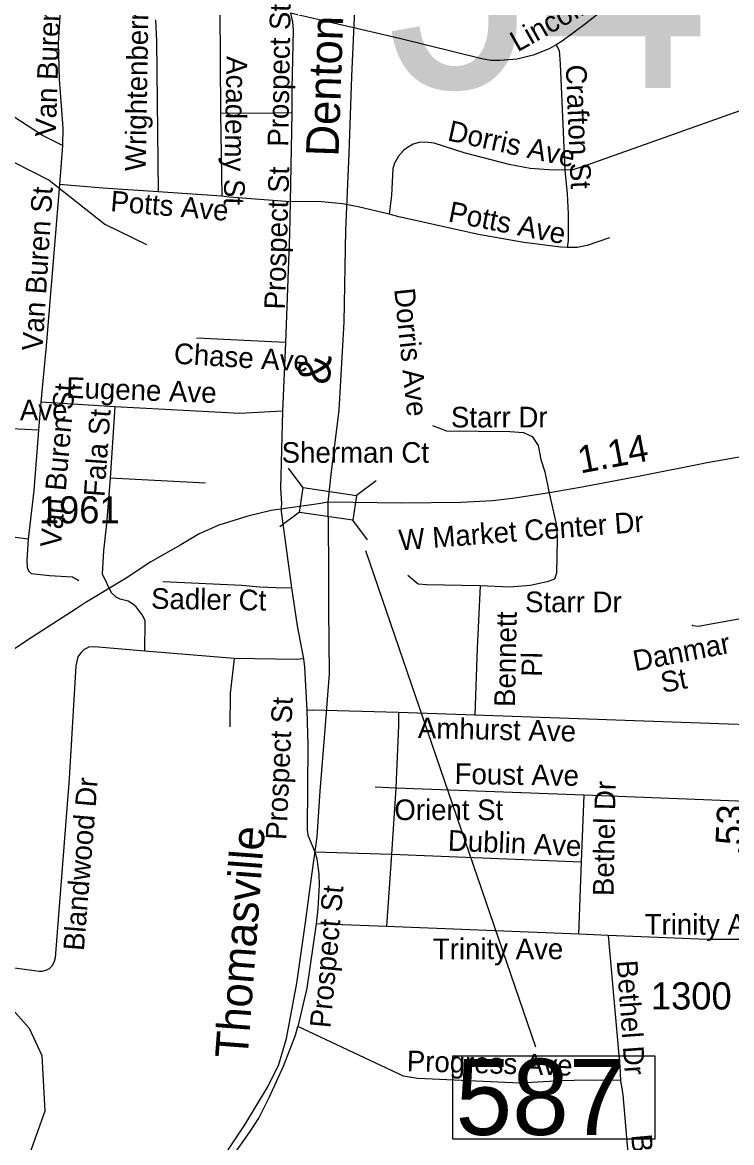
# Model space of a CAD drawing. Extents: x 1662474 to 1856135, y 779280 to 917889.
# Drawn here: x 1695888 to 1699151, y 792320 to 797474 of the extents above; entities that cross this region are included whole.
import ezdxf

# ---------------------------------------------------------------- set-up
doc = ezdxf.new("R2010")
doc.units = 0
for name, color, linetype in [('Exist Hydrographic Misc Water Feature', 7, 'Continuous'), ('Exist Railroad Mainline', 7, 'Continuous'), ('Exist Railroad Mainline Label', 7, 'Continuous'), ('Exist Road Non-System Structure Non-Sys Other Number Label', 7, 'Continuous'), ('Exist Road Non-System Type 51', 7, 'Continuous'), ('Exist Road Non-System Type 51 Label', 7, 'Continuous'), ('Exist Road Secondary Mileage Hundredths English Label', 7, 'Continuous'), ('Exist Road Secondary Mileage Tenths English Label', 7, 'Continuous'), ('Exist Road Secondary Structure Standard Bridge CELL', 7, 'Continuous'), ('Exist Road Secondary Structure Standard Bridge Number Label', 7, 'Continuous'), ('Exist Road Secondary Type 51 Label', 7, 'Continuous'), ('Exist Road Secondary Type 51 Number Label', 7, 'Continuous'), ('Exist Road Secondary Type 51 Undivided 4 Lane Attributed', 7, 'Continuous')]:
    doc.layers.add(name, color=color, linetype=linetype)

msp = doc.modelspace()

# ---------------------------------------------------------------- linework, layer by layer
at = {"layer": 'Exist Hydrographic Misc Water Feature'}
for points in [[(1695762.9, 796874), (1696011.8, 796747.6), (1696267.8, 796545.3), (1696458.8, 796452.8)], [(1690243.7, 793625), (1690261.8, 793742.8), (1690503.7, 793813.4), (1690978.7, 793826.6), (1692288.8, 793921.5), (1692512.8, 793841.5), (1693269.8, 793691.5), (1693377.8, 793623.6), (1693651.8, 793522.9), (1693959.8, 793487.1), (1694548.8, 793222.4), (1695381.8, 793202.2), (1695730.8, 793057.2), (1695919.9, 792846.6), (1695976.9, 792720.7), (1695990.8, 792464.4), (1695921.8, 792272.1)]]:
    msp.add_lwpolyline(points, dxfattribs=at)
at = {"layer": 'Exist Railroad Mainline'}
msp.add_lwpolyline([(1696759.8, 792173), (1696911.1, 792402), (1697014, 792571.6), (1697066.7, 792675.2), (1697103.3, 792799.2), (1697150.8, 793053), (1697190.3, 793332.8), (1697215.4, 793516.8), (1697244.6, 793726.6), (1697257.7, 793936.4), (1697281.6, 794220.5), (1697300.9, 794476.5), (1697298.5, 794772.4), (1697297.5, 794998.7), (1697295.6, 795266), (1697307.9, 795394.4), (1697345.6, 795690.4), (1697367.9, 796094.3), (1697376.2, 796518.6), (1697392.2, 796870.5), (1697404.3, 797224.4), (1697418.1, 797530.7)], dxfattribs=at)
at = {"layer": 'Exist Road Non-System Type 51'}
for p, q in [((1696796.6, 797537), (1696799.2, 797055.7)), ((1696799.2, 797055.7), (1696805.5, 796674.9)), ((1697128.1, 797057.8), (1697119.6, 796648.1)), ((1696072.5, 796907.1), (1696058.9, 796727.9)), ((1696805.5, 796674.9), (1696513.4, 796694.8)), ((1697098.4, 796001.4), (1696689.5, 796020.5)), ((1697098.4, 796001.4), (1697084.5, 795685.6)), ((1695972.8, 795726), (1695962.2, 795597.7)), ((1696313.4, 795704.8), (1695972.8, 795726)), ((1696313.4, 795704.8), (1696292.6, 795376.7)), ((1695962.2, 795597.7), (1695602.1, 795616)), ((1696731, 795354.7), (1696292.6, 795376.7)), ((1697079.2, 795223.2), (1697126.2, 794872.5)), ((1696862.8, 794547.6), (1696451.5, 794580.9)), ((1697618.9, 794300.4), (1697969.9, 794288.8)), ((1697969.9, 794288.8), (1699269, 794241.8)), ((1697606.4, 793951.2), (1697510.8, 793955.2)), ((1697606.4, 793951.2), (1697585.6, 793647.4)), ((1698473.2, 793919.2), (1697606.4, 793951.2)), ((1698460.9, 793612.2), (1698473.2, 793919.2)), ((1699255.9, 793887.8), (1698473.2, 793919.2)), ((1697233.4, 793657.9), (1697585.6, 793647.4)), ((1697585.6, 793647.4), (1697562.5, 793314.2)), ((1697585.6, 793647.4), (1698460.9, 793612.2)), ((1698448.6, 793278.9), (1698460.9, 793612.2)), ((1697562.5, 793314.2), (1697240.4, 793325.9)), ((1698448.6, 793278.9), (1697562.5, 793314.2)), ((1698582.4, 793273.1), (1698448.6, 793278.9))]:
    msp.add_line(p, q, dxfattribs=at)
for points in [[(1698802.4, 798257.2), (1698810, 797982.9), (1698803.1, 797941.2), (1698787.1, 797898.7), (1698732.2, 797797.4), (1698655.4, 797669.9), (1698595, 797580.9), (1698537, 797513.7), (1698479.5, 797468), (1698371.4, 797387.9), (1698343.4, 797371.4)], [(1696099, 797694.2), (1696085.4, 797678.8), (1696077.5, 797653.5), (1696060.4, 797501.6), (1696052.5, 797379.8), (1696056.5, 797213.4), (1696073.5, 796987.4), (1696072.5, 796907.1)], [(1697120.8, 797517.1), (1697130.5, 797476.1), (1697133.6, 797439.9), (1697127.1, 797167.8), (1697128.1, 797057.8)], [(1698343.4, 797371.4), (1698311, 797351.7), (1698237.9, 797323.1), (1698165.1, 797305), (1698084, 797299.2), (1698042.8, 797299.2), (1698001.6, 797306.4), (1697623.6, 797399.8), (1697120.8, 797517.1)], [(1696501.1, 797485), (1696505.6, 797387.9), (1696513.4, 796694.8)], [(1698343.4, 797371.4), (1698356.9, 797344.4), (1698362.5, 797284), (1698383.5, 796794.8)], [(1699559.4, 797199.5), (1698472.6, 796811.9), (1698421, 796795.2), (1698383.5, 796794.8)], [(1696072.5, 796907.1), (1695980.6, 796953.9), (1695689.2, 797141.8)], [(1697128.1, 797057.8), (1696973.8, 797055.1), (1696799.2, 797055.7)], [(1698383.5, 796794.8), (1698310.2, 796795.2), (1698224.9, 796802.4), (1698127.4, 796820.5), (1697920.8, 796873.8), (1697782.1, 796917.6), (1697739.4, 796922.6), (1697714.1, 796921.5), (1697685.6, 796913.2), (1697660.6, 796898.9), (1697642.2, 796884.8), (1697618.4, 796857.8), (1697600.5, 796826.2), (1697592.6, 796801.1), (1697585.9, 796677.7), (1697575.4, 796591.6)], [(1698383.5, 796794.8), (1698394.2, 796685.9), (1698399.2, 796593.8), (1698398.6, 796469.9), (1698394.5, 796438.1)], [(1696058.9, 796727.9), (1695997.4, 795985.4), (1695972.8, 795726)], [(1696513.4, 796694.8), (1696258.9, 796710.8), (1696058.9, 796727.9)], [(1697119.6, 796648.1), (1696839.1, 796669.9), (1696805.5, 796674.9)], [(1697119.6, 796648.1), (1697117.4, 796499.5), (1697098.4, 796001.4)], [(1697575.4, 796591.6), (1697432.6, 796625.2), (1697360.9, 796638.9), (1697263.5, 796648.1), (1697161.6, 796649.9), (1697119.6, 796648.1)], [(1698394.5, 796438.1), (1698365.9, 796439.4), (1698194.8, 796461.4), (1697987.1, 796497.4), (1697620, 796579.5), (1697575.4, 796591.6)], [(1698589, 796482.4), (1698485.9, 796448.1), (1698440.6, 796438.6), (1698394.5, 796438.1)], [(1697084.5, 795685.6), (1696887.9, 795673.8), (1696313.4, 795704.8)], [(1697084.5, 795685.6), (1697075.4, 795328.9), (1697080.9, 795261.2), (1697079, 795242.4), (1697079.2, 795223.2)], [(1695962.2, 795597.7), (1695941, 795319.8), (1695914.8, 795095.9)], [(1697775.1, 795618.9), (1697838.6, 795594.2), (1698130.4, 795591.1), (1698192.9, 795587.7), (1698233.6, 795569.4), (1698261.6, 795526.9), (1698273.8, 795462.5), (1698291.9, 795406.9), (1698311.6, 795308.4)], [(1696292.6, 795376.7), (1696275.1, 795166.7), (1696261.4, 795043.4), (1696254.4, 794936.8), (1696296.9, 794851.2)], [(1698311.6, 795308.4), (1698343.1, 795166.2), (1698349.1, 795098.5), (1698346.1, 794940.5), (1698335.6, 794911.9), (1698302.4, 794899.8), (1698224.1, 794883), (1698130.8, 794875.7), (1697993.6, 794881.4)], [(1695914.8, 795095.9), (1695843.9, 795105), (1695580.4, 795122.6)], [(1695914.8, 795095.9), (1695908.1, 795000.1), (1695909.5, 794967.5), (1695916.1, 794950.2), (1695927.9, 794938.4), (1696012.1, 794928.9), (1696118.4, 794922.6), (1696147, 794906.6)], [(1697993.6, 794881.4), (1697747.2, 794886.7), (1697709.5, 794889), (1697661.4, 794928.7)], [(1697126.2, 794872.5), (1697090.1, 794870.4), (1696980.9, 794875.4), (1696897.1, 794883.8), (1696534.9, 794899.5)], [(1697126.2, 794872.5), (1697152, 794696.9), (1697181.4, 794545.2)], [(1697993.6, 794881.4), (1697980.4, 794594.2), (1697969.9, 794288.8)], [(1696451.5, 794580.9), (1696452.2, 794722.6), (1696438.6, 794748.9), (1696412.1, 794784.6), (1696395.4, 794799.2), (1696374.4, 794811.6), (1696337.9, 794820.5), (1696319.5, 794829.4), (1696296.9, 794851.2)], [(1699302.6, 794750.4), (1698997.4, 794695.1), (1698972.4, 794697.4), (1698968.2, 794702.7)], [(1696451.5, 794580.9), (1696220, 794601.4), (1696193.8, 794599.8), (1696172.8, 794589.2), (1696156.5, 794573), (1696143.4, 794555.4), (1696133.9, 794513.7), (1696103.1, 793995.6), (1696038.4, 793170.2), (1696034.9, 793152.6), (1696025.5, 793133.9), (1696010.6, 793119.5), (1695998.8, 793112.9), (1695978.8, 793107.4), (1695964.9, 793107.9), (1695491.9, 793171.2), (1695468, 793185.4), (1695450.1, 793206.7), (1695442.1, 793227.1), (1695439.9, 793243.9), (1695420, 794000.6), (1695415.5, 794088), (1695411.6, 794103.5)], [(1696862.8, 794547.6), (1696844.6, 794386.2), (1696843.1, 794232.9)], [(1697181.4, 794545.2), (1697148.1, 794542.6), (1696862.8, 794547.6)], [(1697181.4, 794545.2), (1697186.6, 794507.9), (1697197.4, 794310)], [(1697197.4, 794310), (1697224.6, 794311.6), (1697618.9, 794300.4)], [(1697197.4, 794310), (1697200.6, 794148.4), (1697198.4, 793760.7), (1697200.6, 793735.2), (1697233.4, 793657.9)], [(1697618.9, 794300.4), (1697618.9, 794239.4), (1697606.4, 793951.2)], [(1697233.4, 793657.9), (1697243.4, 793625.2), (1697252.5, 793554.7), (1697253, 793505.4), (1697247.8, 793395.9), (1697240.4, 793325.9)], [(1697240.4, 793325.9), (1697196.9, 793030.2), (1697155.9, 792854.7)], [(1698582.4, 793273.1), (1698637.2, 792669.7), (1698640.4, 792606.2)], [(1699219.6, 793254.2), (1699037.8, 793254.9), (1698582.4, 793273.1)], [(1695958.9, 790839.2), (1695889.6, 790774.7), (1695920.8, 790884.4), (1695962.5, 790997), (1696034.6, 791162.1), (1696069.9, 791225.1), (1696274.6, 791548.7), (1696349.1, 791662.6), (1696400.6, 791735.9), (1696626.9, 791967.6), (1696674.9, 792022.9), (1696794.2, 792171.2), (1696936, 792370.7), (1696975.1, 792432.9), (1697025.2, 792530.2), (1697089.8, 792672.2), (1697144.9, 792814), (1697155.9, 792854.7)], [(1698640.4, 792606.2), (1698485, 792606.9), (1698368.2, 792603.8), (1698177.4, 792593.5), (1697706.4, 792614.8), (1697641.5, 792625.9), (1697155.9, 792854.7)], [(1698640.4, 792606.2), (1698649.9, 792539.5), (1698699.5, 791968.9)]]:
    msp.add_lwpolyline(points, dxfattribs=at)
at = {"layer": 'Exist Road Secondary Structure Standard Bridge CELL'}
for p, q in [((1697179.9, 795331.9), (1697112.3, 795422.7)), ((1697516.2, 795365.5), (1697425.4, 795298)), ((1697163.4, 795219.9), (1697072.6, 795152.4)), ((1697476.2, 795092.6), (1697408.6, 795183.4))]:
    msp.add_line(p, q, dxfattribs=at)
msp.add_lwpolyline([(1697408.6, 795183.4), (1697163.4, 795219.4), (1697180.2, 795334), (1697425.4, 795298)], close=True, dxfattribs=at)
at = {"layer": 'Exist Road Secondary Structure Standard Bridge Number Label'}
msp.add_line((1697465.9, 795043.8), (1698248.3, 792760.1), dxfattribs=at)
msp.add_lwpolyline([(1697868.4, 792719.6), (1698797.4, 792719.6), (1698797.4, 792335.5), (1697868.4, 792335.5)], close=True, dxfattribs=at)
at = {"layer": 'Exist Road Secondary Type 51 Undivided 4 Lane Attributed'}
msp.add_lwpolyline([(1699351.2, 795502.4), (1699038.5, 795447), (1698723.2, 795384.8), (1698454.4, 795334.5), (1698312.5, 795309.8), (1698143.4, 795284.2), (1698050.5, 795272.3), (1697905.2, 795265.5), (1697633.4, 795262.1), (1697295.6, 795266), (1697250.3, 795259.4), (1697098.6, 795237.2), (1697033.2, 795228.4), (1696925.3, 795201.8), (1696791.6, 795161.2), (1696701.4, 795120.5), (1696616.5, 795071), (1696478.6, 794991.5), (1696365.4, 794917.3), (1696176.3, 794804.1), (1696135.9, 794776.3), (1695916.6, 794634.1), (1695768.5, 794536.5)], dxfattribs=at)

# ---------------------------------------------------------------- texts
at = {"layer": 'Exist Railroad Mainline Label'}
for s, rotation, p in [('Denton', 88.0418, (1697342.4, 796855.1)), ('&', 86.8398, (1697302.7, 795806.1)), ('Thomasville', 85.6883, (1696923.9, 792704))]:
    msp.add_text(s, height=150, rotation=rotation, dxfattribs=at).set_placement(p)
at = {"layer": 'Exist Road Non-System Structure Non-Sys Other Number Label'}
msp.add_text('J477', height=1049.86, dxfattribs=at).set_placement((1697564.8, 797172.3))
at = {"layer": 'Exist Road Non-System Type 51 Label'}
for s, rotation, p in [('Wrightenberry St', 89.0384, (1696455.4, 796789.3)), ('Van Buren St', 88.1023, (1696041.6, 796946.8)), ('Lincoln Dr', 29.4315, (1698166.4, 797335.6)), ('Prospect St', 89.0384, (1697111.1, 796901.5)), ('Academy St', 268.8875, (1696828, 797319.1)), ('Crafton St', 272.392, (1698387.7, 797277.8)), ('Dorris Ave', 347.79, (1697839.7, 796931.5)), ('Prospect St', 88.2107, (1697095.7, 796152)), ('Van Buren St', 86.3881, (1695980.4, 795960.6)), ('Potts Ave', 355.2894, (1696290.8, 796605.3)), ('Potts Ave', 348.8304, (1697843.1, 796558.4)), ('Dorris Ave', 275.886, (1697598.3, 796246.8)), ('Chase Ave', 356.543, (1696583.1, 795904.2)), ('Van Buren St', 85.0331, (1696064.8, 795055.5)), ('Eugene Ave', 357.9828, (1696088.2, 795747.1)), ('Fala St', 85.8741, (1696265.1, 795289)), ('Sadler Ct', 359.0759, (1696479.6, 794776.4)), ('Bennett', 88.8699, (1698154.1, 794323.7)), ('Danmar', 10.9059, (1698707.2, 794488.4)), ('    Pl', 88.8699, (1698276.1, 794321.3)), ('   St', 10.9059, (1698730.3, 794368.7)), ('Prospect St', 87.3941, (1697102.2, 793711.2)), ('Amhurst Ave', 358.7177, (1697707.1, 794181.2)), ('Foust Ave', 359.0833, (1697876.2, 793970.4)), ('Blandwood Dr', 85.3263, (1696170.7, 793199.9)), ('Bethel Dr', 88.912, (1698607.4, 793453.9)), ('Dublin Ave', 357.5649, (1697844, 793663.6)), ('Prospect St', 84.7071, (1697304.8, 792844.6)), ('Trinity Ave', 359.9919, (1698751, 793276.5)), ('Bethel Dr', 274.1017, (1698622.3, 793156.2)), ('Progress Ave', 358.4164, (1697655.6, 792648.8)), ('Bethel Dr', 275.1784, (1698688.4, 792354.9))]:
    msp.add_text(s, height=95, rotation=rotation, dxfattribs=at).set_placement(p)
for s, p in [('Eugene Ave', (1695403.3, 795643.4)), ('Starr Dr', (1697859.6, 795610.4)), ('Sherman Ct', (1697080.9, 795447.8)), ('Starr Dr', (1698200.7, 794760.3)), ('Orient St', (1697599.2, 793803.9)), ('Trinity Ave', (1697776.4, 793164))]:
    msp.add_text(s, height=95, dxfattribs=at).set_placement(p)
at = {"layer": 'Exist Road Secondary Mileage Hundredths English Label'}
msp.add_text('1.14', height=125, rotation=10.5922, dxfattribs=at).set_placement((1698455.4, 795398.3))
at = {"layer": 'Exist Road Secondary Mileage Tenths English Label'}
msp.add_text('.53', height=125, rotation=87.4288, dxfattribs=at).set_placement((1699199.3, 793640))
at = {"layer": 'Exist Road Secondary Structure Standard Bridge Number Label'}
msp.add_text('587', height=350, dxfattribs=at).set_placement((1697881, 792355.3))
at = {"layer": 'Exist Road Secondary Type 51 Label'}
msp.add_text('W Market Center Dr', height=95, rotation=4.3944, dxfattribs=at).set_placement((1697623.2, 795044.3))
at = {"layer": 'Exist Road Secondary Type 51 Number Label'}
for s, p in [('1961', (1695963.7, 795168.8)), ('1300', (1698779.5, 792932.5))]:
    msp.add_text(s, height=125, dxfattribs=at).set_placement(p)

doc.saveas('drawing.dxf')
